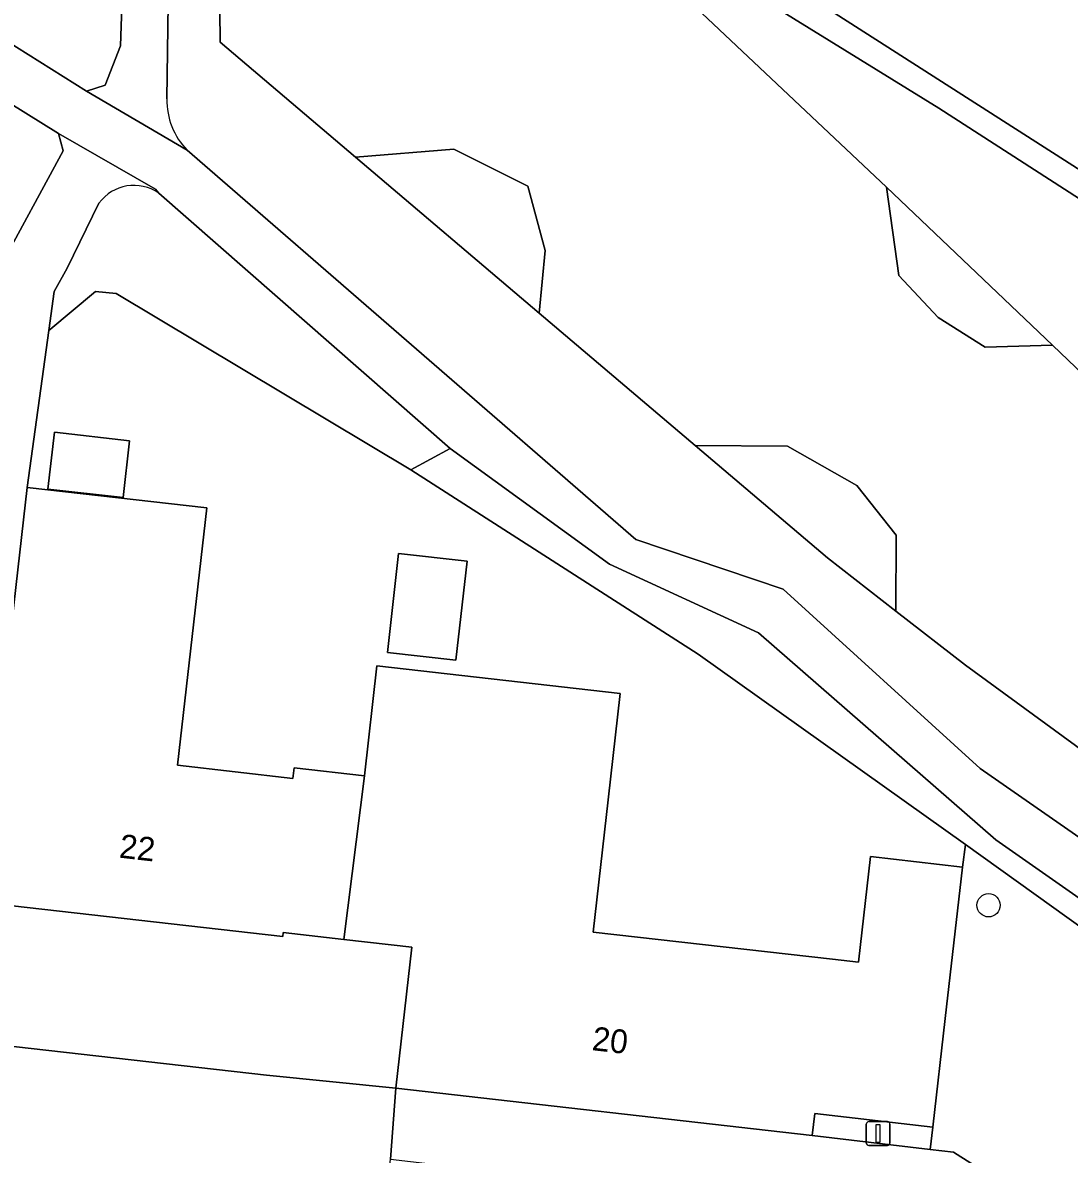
# Model space of a CAD drawing. Extents: x 162396 to 163643, y 386452 to 387406.
# Drawn here: x 162755.65 to 162799.66, y 386820.85 to 386868.43 of the extents above; entities that cross this region are included whole.
import ezdxf

# ---------------------------------------------------------------- set-up
doc = ezdxf.new("R2010")
doc.units = 0
for name, color, linetype in [('IMGEO_Boom', 7, 'Continuous'), ('IMGEO_Erf', 7, 'Continuous'), ('IMGEO_Groenvoorziening', 7, 'Continuous'), ('IMGEO_Lichtmast', 7, 'Continuous'), ('IMGEO_Pand', 7, 'Continuous'), ('IMGEO_Pand_nummerreeks', 7, 'Continuous'), ('IMGEO_Rijbaan_lokaal_gesloten', 7, 'Continuous'), ('IMGEO_Rijbaan_lokaal_open', 7, 'Continuous'), ('IMGEO_Voetpad_gesloten', 7, 'Continuous'), ('IMGEO_Voetpad_open', 7, 'Continuous')]:
    doc.layers.add(name, color=color, linetype=linetype)

msp = doc.modelspace()

# ---------------------------------------------------------------- linework, layer by layer
at = {"layer": 'IMGEO_Boom'}
msp.add_circle((162796.267, 386831.323), 0.489, dxfattribs=at)
at = {"layer": 'IMGEO_Erf'}
for points in [[(162784.059, 386841.886), (162771.971, 386849.624), (162759.59, 386857.037), (162758.71, 386857.127), (162756.752, 386855.489), (162755.84, 386848.887), (162763.395, 386848.027), (162762.164, 386837.21), (162767.018, 386836.657), (162767.069, 386837.104), (162770.023, 386836.767), (162770.548, 386841.385), (162780.782, 386840.221), (162780.274, 386835.752), (162779.642, 386830.196), (162789.701, 386829.051), (162790.793, 386828.927), (162791.303, 386833.372), (162795.177, 386832.927), (162795.29, 386833.881)], [(162756.717, 386848.82), (162756.989, 386851.206), (162760.151, 386850.846), (162759.879, 386848.46)], [(162770.988, 386841.952), (162771.462, 386846.115), (162774.345, 386845.788), (162773.871, 386841.624)], [(162772.012, 386829.563), (162769.151, 386829.889), (162766.607, 386830.179), (162766.587, 386830.007), (162753.857, 386831.456), (162753.557, 386828.595), (162753.154, 386825.624), (162765.904, 386824.181), (162771.337, 386823.634)], [(162793.924, 386821.998), (162788.956, 386822.567), (162788.85, 386821.642), (162793.816, 386821.057)]]:
    msp.add_lwpolyline(points, close=True, dxfattribs=at)
at = {"layer": 'IMGEO_Groenvoorziening'}
for points in [[(162760.109, 386877.357), (162760.12, 386880.581), (162762.667, 386884.765), (162759.659, 386886.742), (162750.954, 386874.003), (162750.261, 386872.951), (162750.116, 386872.272), (162750.104, 386871.666), (162750.201, 386871.29), (162750.961, 386870.189), (162758.337, 386865.545), (162759.124, 386865.805), (162759.762, 386867.447)], [(162804.526, 386849.538), (162806.486, 386847.667), (162812.215, 386842.196), (162812.305, 386840.927), (162812.269, 386839.352), (162811.903, 386836.838), (162811.668, 386836.008), (162811.41, 386835.098), (162809.015, 386831.4), (162795.291, 386841.411), (162792.362, 386843.692), (162789.496, 386845.923), (162783.929, 386850.65), (162777.372, 386856.218), (162769.653, 386862.773), (162763.956, 386867.61), (162763.832, 386879.691), (162769.322, 386876.812), (162777.111, 386872.728), (162780.313, 386871.049), (162784.213, 386868.82), (162791.979, 386861.518), (162798.949, 386854.863)], [(162777.372, 386856.218), (162777.627, 386858.843), (162776.9, 386861.547), (162773.782, 386863.107), (162769.653, 386862.773)], [(162798.949, 386854.863), (162791.979, 386861.518), (162792.488, 386857.803), (162794.151, 386856.035), (162796.125, 386854.787)], [(162786.596, 386842.77), (162780.332, 386845.664), (162773.627, 386850.519), (162771.971, 386849.624), (162784.059, 386841.886), (162795.29, 386833.881), (162809.763, 386823.512), (162810.358, 386824.421), (162796.575, 386834.081)], [(162792.362, 386843.692), (162792.384, 386846.884), (162790.721, 386848.964), (162787.811, 386850.627), (162783.929, 386850.65), (162789.496, 386845.923)], [(162793.924, 386821.998), (162793.816, 386821.057), (162794.788, 386820.942), (162804.178, 386814.988), (162809.763, 386823.512), (162795.29, 386833.881), (162795.177, 386832.927), (162794.448, 386826.569)]]:
    msp.add_lwpolyline(points, close=True, dxfattribs=at)
for points in [[(162820.551, 386847.833), (162819.334, 386848.618), (162794.171, 386864.833), (162784.116, 386871.052), (162764.442, 386883.713), (162761.955, 386879.712), (162761.867, 386876.231), (162761.72, 386865.221)], [(162763.832, 386879.691), (162763.956, 386867.61), (162769.653, 386862.773), (162773.782, 386863.107), (162776.9, 386861.547), (162777.627, 386858.843), (162777.372, 386856.218), (162783.929, 386850.65), (162787.811, 386850.627), (162790.721, 386848.964), (162792.384, 386846.884), (162792.362, 386843.692), (162795.291, 386841.411), (162809.015, 386831.4), (162811.41, 386835.098), (162811.668, 386836.008), (162807.141, 386840.748), (162804.526, 386849.538), (162798.949, 386854.863), (162796.125, 386854.787), (162794.151, 386856.035), (162792.488, 386857.803), (162791.979, 386861.518), (162784.213, 386868.82)], [(162757.354, 386863.038), (162757.155, 386863.774), (162750.271, 386868.04)], [(162762.57, 386863.069), (162781.435, 386846.7), (162787.626, 386844.619), (162795.909, 386837.076), (162811.483, 386826.237), (162819.797, 386839.145), (162820.19, 386839.921), (162821.929, 386842.61)], [(162740.897, 386856.129), (162754.322, 386856.814), (162754.632, 386858.046), (162757.354, 386863.038)], [(162758.86, 386860.841), (162757.53, 386858.109), (162756.978, 386857.122), (162756.752, 386855.489), (162758.71, 386857.127), (162759.59, 386857.037), (162771.971, 386849.624), (162773.627, 386850.519), (162761.38, 386861.259)]]:
    msp.add_lwpolyline(points, dxfattribs=at)
for centre, radius, start, end in [((162764.664, 386865.14), 2.945, 178.425, 224.6812), ((162760.335, 386859.755), 1.832, 55.2122, 143.624)]:
    msp.add_arc(centre, radius, start, end, dxfattribs=at)
at = {"layer": 'IMGEO_Lichtmast'}
for p, q in [((162791.127, 386821.327), (162791.127, 386822.127)), ((162791.127, 386822.127), (162791.127, 386821.327)), ((162791.227, 386822.227), (162792.017, 386822.227)), ((162792.017, 386822.227), (162791.227, 386822.227)), ((162792.117, 386822.127), (162792.117, 386821.327)), ((162792.117, 386821.327), (162792.117, 386822.127)), ((162792.017, 386821.227), (162791.227, 386821.227)), ((162791.227, 386821.227), (162792.017, 386821.227))]:
    msp.add_line(p, q, dxfattribs=at)
msp.add_lwpolyline([(162791.547, 386822.102), (162791.697, 386822.102), (162791.697, 386821.352), (162791.547, 386821.352), (162791.547, 386822.102)], dxfattribs=at)
for centre, start, end in [((162791.227, 386822.127), 90, 180), ((162791.227, 386822.127), 90, 180), ((162792.017, 386822.127), 0, 90), ((162792.017, 386822.127), 360, 90), ((162791.227, 386821.327), 180, 270), ((162791.227, 386821.327), 180, 270), ((162792.017, 386821.327), 270, 0), ((162792.017, 386821.327), 270, 0)]:
    msp.add_arc(centre, 0.1, start, end, dxfattribs=at)
at = {"layer": 'IMGEO_Pand'}
for points in [[(162756.717, 386848.82), (162759.879, 386848.46), (162760.151, 386850.846), (162756.989, 386851.206)], [(162753.857, 386831.456), (162766.587, 386830.007), (162766.607, 386830.179), (162769.151, 386829.889), (162770.023, 386836.767), (162767.069, 386837.104), (162767.018, 386836.657), (162762.164, 386837.21), (162763.395, 386848.027), (162755.84, 386848.887)], [(162770.988, 386841.952), (162773.871, 386841.624), (162774.345, 386845.788), (162771.462, 386846.115)], [(162794.448, 386826.569), (162795.177, 386832.927), (162791.303, 386833.372), (162790.793, 386828.927), (162789.701, 386829.051), (162779.642, 386830.196), (162780.274, 386835.752), (162780.782, 386840.221), (162770.548, 386841.385), (162770.023, 386836.767), (162769.151, 386829.889), (162772.012, 386829.563), (162771.337, 386823.634), (162788.85, 386821.642), (162788.956, 386822.567), (162793.924, 386821.998)]]:
    msp.add_lwpolyline(points, close=True, dxfattribs=at)
at = {"layer": 'IMGEO_Rijbaan_lokaal_gesloten'}
msp.add_lwpolyline([(162732.519, 386905.283), (162732.519, 386905.283), (162745.396, 386897.065), (162757.506, 386889.413), (162768.474, 386882.429), (162784.448, 386872.261), (162817.434, 386851.158), (162819.973, 386849.537), (162823.672, 386855.407), (162820.21, 386857.595), (162786.675, 386879.214), (162755.243, 386899.437), (162737.16, 386911.071), (162735.144, 386908.29), (162732.519, 386905.283)], dxfattribs=at)
at = {"layer": 'IMGEO_Rijbaan_lokaal_open'}
msp.add_lwpolyline([(162755.5, 386804.302), (162755.652, 386804.589), (162755.829, 386804.862), (162756.029, 386805.118), (162756.252, 386805.355), (162756.495, 386805.571), (162756.756, 386805.764), (162757.033, 386805.934), (162757.325, 386806.077), (162757.628, 386806.195), (162757.94, 386806.284), (162758.26, 386806.346), (162758.583, 386806.379), (162758.908, 386806.382), (162759.232, 386806.357), (162767.293, 386805.44), (162769.364, 386805.198), (162769.693, 386808.085), (162771.126, 386820.646), (162771.337, 386823.634), (162765.904, 386824.181), (162753.154, 386825.624)], dxfattribs=at)
at = {"layer": 'IMGEO_Voetpad_gesloten'}
for points in [[(162761.867, 386876.231), (162761.955, 386879.712), (162764.442, 386883.713), (162762.667, 386884.765), (162760.12, 386880.581), (162760.109, 386877.357), (162759.762, 386867.447), (162759.124, 386865.805), (162758.337, 386865.545), (162762.57, 386863.069)], [(162761.72, 386865.221), (162761.867, 386876.231)], [(162743.699, 386872.388), (162750.271, 386868.04), (162757.155, 386863.774), (162761.244, 386861.423), (162761.38, 386861.259), (162773.627, 386850.519), (162780.332, 386845.664), (162786.596, 386842.77), (162796.575, 386834.081), (162810.358, 386824.421), (162811.483, 386826.237), (162795.909, 386837.076), (162787.626, 386844.619), (162781.435, 386846.7), (162762.57, 386863.069), (162758.337, 386865.545), (162750.961, 386870.189)], [(162761.38, 386861.259), (162761.244, 386861.423), (162757.155, 386863.774), (162757.354, 386863.038), (162754.632, 386858.046), (162754.322, 386856.814), (162753.941, 386855.492), (162751.888, 386837.061), (162751.463, 386837.087), (162750.858, 386831.752), (162753.857, 386831.456), (162755.84, 386848.887), (162756.752, 386855.489)], [(162756.752, 386855.489), (162756.978, 386857.122), (162757.53, 386858.109), (162758.86, 386860.841)]]:
    msp.add_lwpolyline(points, dxfattribs=at)
for centre, radius, start, end in [((162764.664, 386865.14), 2.945, 178.425, 224.6812), ((162760.335, 386859.755), 1.832, 55.2122, 143.624)]:
    msp.add_arc(centre, radius, start, end, dxfattribs=at)
at = {"layer": 'IMGEO_Voetpad_open'}
for points in [[(162821.993, 386848.16), (162819.973, 386849.537), (162817.434, 386851.158), (162784.448, 386872.261), (162768.474, 386882.429), (162757.506, 386889.413), (162745.396, 386897.065), (162732.519, 386905.283), (162732.519, 386905.283), (162731.775, 386904.431)], [(162731.775, 386904.431), (162740.429, 386898.928), (162749.873, 386892.893), (162758.066, 386887.745), (162758.12, 386887.711), (162759.613, 386886.773), (162759.659, 386886.742), (162762.667, 386884.765), (162764.442, 386883.713), (162784.116, 386871.052), (162794.171, 386864.833), (162819.334, 386848.618), (162820.551, 386847.833), (162820.846, 386847.701), (162824.327, 386845.024)]]:
    msp.add_lwpolyline(points, dxfattribs=at)
msp.add_lwpolyline([(162794.788, 386820.942), (162793.816, 386821.057), (162788.85, 386821.642), (162771.337, 386823.634), (162771.126, 386820.646), (162773.399, 386820.382), (162776.506, 386819.973), (162793.802, 386817.953), (162802.507, 386812.457), (162804.178, 386814.988)], close=True, dxfattribs=at)

# ---------------------------------------------------------------- texts
at = {"layer": 'IMGEO_Pand_nummerreeks'}
for s, rotation, p in [('22', 353.5062, (162759.683, 386833.329)), ('20', 353.5108, (162779.563, 386825.235))]:
    msp.add_text(s, height=1, rotation=rotation, dxfattribs=at).set_placement(p)

doc.saveas('drawing.dxf')
